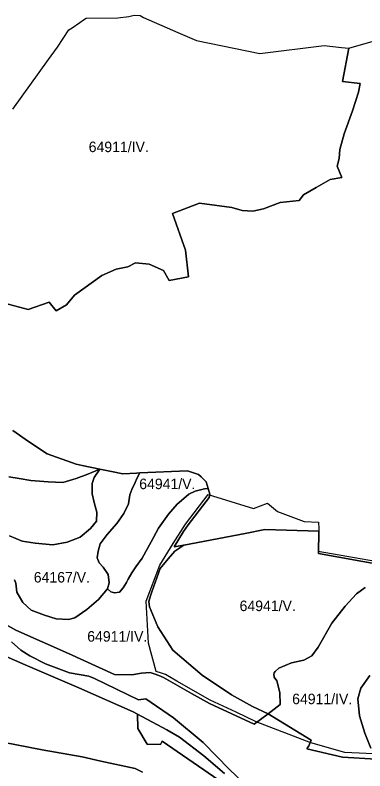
# Model space of a CAD drawing. Extents: x -521621 to -516761, y -1190184 to -1184927.
# Drawn here: x -520185 to -519686, y -1187011 to -1185932 of the extents above; entities that cross this region are included whole.
import ezdxf

# ---------------------------------------------------------------- set-up
doc = ezdxf.new("R2010")
doc.units = 0
doc.layers.add('BPEJ_s', color=7, linetype='Continuous')
doc.layers.add('odvodneni_s', color=7, linetype='Continuous')

msp = doc.modelspace()

# ---------------------------------------------------------------- linework, layer by layer
at = {"layer": 'BPEJ_s'}
for p, q in [((-520238.4, -1186779.9), (-520184.6, -1186810)), ((-520184.6, -1186810), (-520109.4, -1186843.3)), ((-520177.2, -1186838.5), (-520190.8, -1186826.8)), ((-520164.5, -1186846.6), (-520177.2, -1186838.5)), ((-520142.1, -1186858), (-520164.5, -1186846.6)), ((-520109.4, -1186843.3), (-520043.4, -1186873.2)), ((-520107.7, -1186870.7), (-520142.1, -1186858)), ((-520079.9, -1186875.5), (-520107.7, -1186870.7)), ((-520043.4, -1186873.2), (-520018.6, -1186873.6)), ((-520018.6, -1186873.6), (-520005, -1186871.4)), ((-520005, -1186871.4), (-519992.7, -1186870.6)), ((-519992.7, -1186870.6), (-519986.9, -1186872.5)), ((-519986.9, -1186872.5), (-519979.9, -1186874.8)), ((-520072.2, -1186878.9), (-520079.9, -1186875.5)), ((-520009.1, -1186909.3), (-520072.2, -1186878.9)), ((-519979.9, -1186874.8), (-519973.3, -1186877.6)), ((-519973.3, -1186877.6), (-519933.4, -1186900.2)), ((-519933.4, -1186900.2), (-519907.6, -1186914.7)), ((-519998.9, -1186908.1), (-520009.1, -1186909.3)), ((-519959.1, -1186935.4), (-519998.9, -1186908.1)), ((-519907.6, -1186914.7), (-519844, -1186944.4)), ((-520009.9, -1186950.2), (-520010.6, -1186930.1)), ((-520010.6, -1186930.1), (-519968.9, -1186952.1)), ((-519916.6, -1186970.3), (-519959.1, -1186935.4)), ((-519844, -1186944.4), (-519823.9, -1186929.6)), ((-519823.9, -1186929.6), (-519762.3, -1186967)), ((-519996.6, -1186972.9), (-520009.9, -1186950.2)), ((-519968.9, -1186952.1), (-519950.4, -1186962.7)), ((-519975.4, -1186968.4), (-519977.6, -1186973.3)), ((-519894.5, -1187024.1), (-519975.4, -1186968.4)), ((-519950.4, -1186962.7), (-519915.9, -1186989.2)), ((-519879.1, -1187008.9), (-519916.6, -1186970.3)), ((-519762.3, -1186967), (-519765.9, -1186974.9)), ((-519977.6, -1186973.3), (-519996.6, -1186972.9)), ((-519765.9, -1186974.9), (-519768.5, -1186979.4)), ((-519768.5, -1186979.4), (-519717.5, -1186991.5)), ((-519915.9, -1186989.2), (-519886.2, -1187014.6)), ((-519717.5, -1186991.5), (-519669.4, -1186994.1)), ((-519859.4, -1187027.5), (-519879.1, -1187008.9))]:
    msp.add_line(p, q, dxfattribs=at)
for points in [[(-520188.5, -1186066.3), (-520137.8, -1185995.6), (-520124.9, -1185977.6), (-520108.5, -1185953.2), (-520104.1, -1185950.1), (-520093.2, -1185942.6), (-520087.7, -1185938.8), (-520084.1, -1185936.3), (-520038.5, -1185935.8), (-520023.1, -1185934), (-520015.2, -1185932), (-520007, -1185932.6), (-520002, -1185935.2), (-519952.9, -1185956.6), (-519926.2, -1185968.3), (-519835.9, -1185987), (-519743.7, -1185975.4), (-519719.3, -1185978.2), (-519708.8, -1185979.4), (-519717.6, -1186026.9), (-519692.5, -1186029.7), (-519694.9, -1186042.2), (-519703.6, -1186068.6), (-519715.4, -1186101.7), (-519721.3, -1186123.8), (-519722.4, -1186136.5), (-519725.5, -1186147.7), (-519718.5, -1186163.7), (-519735.5, -1186166.9), (-519755.4, -1186178.3), (-519773.2, -1186188.4), (-519779.6, -1186196.5), (-519806.9, -1186199.7), (-519830.5, -1186208.5), (-519845.8, -1186211.7), (-519861, -1186210.9), (-519875.8, -1186206.8), (-519922.1, -1186200.5), (-519960.7, -1186215.1), (-519942.2, -1186267.5), (-519937.7, -1186305.7), (-519965.5, -1186310.8), (-519973.3, -1186296.6), (-519993.8, -1186287.6), (-520013.4, -1186285.8), (-520024.6, -1186291.4), (-520041.1, -1186294.9), (-520061.5, -1186303.9), (-520100.6, -1186331.8), (-520112.1, -1186345.7), (-520126.7, -1186354), (-520136.7, -1186342), (-520166.8, -1186352.1), (-520217.3, -1186338.9)], [(-520217.3, -1186338.9), (-520166.8, -1186352.1), (-520136.7, -1186342), (-520126.7, -1186354), (-520112.1, -1186345.7), (-520100.6, -1186331.8), (-520061.5, -1186303.9), (-520041.1, -1186294.9), (-520024.6, -1186291.4), (-520013.4, -1186285.8), (-519993.8, -1186287.6), (-519973.3, -1186296.6), (-519965.5, -1186310.8), (-519937.7, -1186305.7), (-519942.2, -1186267.5), (-519960.7, -1186215.1), (-519922.1, -1186200.5), (-519875.8, -1186206.8), (-519861, -1186210.9), (-519845.8, -1186211.7), (-519830.5, -1186208.5), (-519806.9, -1186199.7), (-519779.6, -1186196.5), (-519773.2, -1186188.4), (-519755.4, -1186178.3), (-519735.5, -1186166.9), (-519718.5, -1186163.7), (-519725.5, -1186147.7), (-519722.4, -1186136.5), (-519721.3, -1186123.8), (-519715.4, -1186101.7), (-519703.6, -1186068.6), (-519694.9, -1186042.2), (-519692.5, -1186029.7), (-519717.6, -1186026.9), (-519708.8, -1185979.4), (-519673.8, -1185969.3)], [(-520188.8, -1186525.2), (-520166.1, -1186540.8), (-520139.9, -1186558.3), (-520098, -1186573.1), (-520089.5, -1186574.9), (-520064.2, -1186580), (-520081.7, -1186587.3), (-520098.2, -1186593.7), (-520117.3, -1186599), (-520138.1, -1186598.5), (-520163.1, -1186596.4), (-520179.6, -1186593.7), (-520194.5, -1186591.1)], [(-519659.7, -1186717.4), (-519752.1, -1186700.7), (-519751.3, -1186668.7), (-519828.5, -1186666.5), (-519856.9, -1186671.8), (-519944.3, -1186688.5), (-519958.3, -1186691.2), (-519944.9, -1186669.1), (-519938.3, -1186659.7), (-519908.1, -1186620.4), (-519907, -1186615.8), (-519909.6, -1186607.6), (-519912.6, -1186598.3), (-519919.7, -1186591.1), (-519923.6, -1186587.6), (-519939.1, -1186582.5), (-520007.3, -1186585.5), (-520011.9, -1186585.7), (-520031.5, -1186586.8), (-520047.8, -1186583.3), (-520064.2, -1186580), (-520089.5, -1186574.9), (-520098, -1186573.1), (-520139.9, -1186558.3), (-520166.1, -1186540.8), (-520188.8, -1186525.2)], [(-520194.5, -1186591.1), (-520179.6, -1186593.7), (-520163.1, -1186596.4), (-520138.1, -1186598.5), (-520117.3, -1186599), (-520098.2, -1186593.7), (-520081.7, -1186587.3), (-520064.2, -1186580), (-520072.6, -1186592.1), (-520075.3, -1186600.6), (-520075.3, -1186615.6), (-520072.1, -1186629.9), (-520068.9, -1186641.7), (-520069.4, -1186654.5), (-520077.9, -1186665.1), (-520092.3, -1186677.4), (-520111, -1186684.3), (-520131.7, -1186688), (-520156.7, -1186685.9), (-520175.4, -1186683.2), (-520193.5, -1186675.2)], [(-520193.5, -1186675.2), (-520175.4, -1186683.2), (-520156.7, -1186685.9), (-520131.7, -1186688), (-520111, -1186684.3), (-520092.3, -1186677.4), (-520077.9, -1186665.1), (-520069.4, -1186654.5), (-520068.9, -1186641.7), (-520072.1, -1186629.9), (-520075.3, -1186615.6), (-520075.3, -1186600.6), (-520072.6, -1186592.1), (-520064.2, -1186580), (-520047.8, -1186583.3), (-520031.5, -1186586.8), (-520011.9, -1186585.7), (-520007.3, -1186585.5), (-520011.5, -1186593.3), (-520014.1, -1186599.1), (-520018.6, -1186609.1), (-520021.7, -1186616.8), (-520023.5, -1186629.8), (-520030.3, -1186643.7), (-520040.2, -1186657.6), (-520053.8, -1186673.3), (-520064, -1186686.6), (-520066.8, -1186697.1), (-520068, -1186707), (-520065.2, -1186713.8), (-520059.7, -1186720), (-520052.6, -1186730.5), (-520051.3, -1186742.3), (-520053.4, -1186751.1), (-520066.4, -1186766.1), (-520082.8, -1186780.7), (-520100, -1186792.6), (-520109.3, -1186794.8), (-520127, -1186793.7), (-520143.4, -1186788.6), (-520162.3, -1186781.6), (-520174.4, -1186770.6), (-520183.1, -1186755.9), (-520184.5, -1186742.9), (-520186.3, -1186738.1)], [(-520186.3, -1186738.1), (-520184.5, -1186742.9), (-520183.1, -1186755.9), (-520174.4, -1186770.6), (-520162.3, -1186781.6), (-520143.4, -1186788.6), (-520127, -1186793.7), (-520109.3, -1186794.8), (-520100, -1186792.6), (-520082.8, -1186780.7), (-520066.4, -1186766.1), (-520053.4, -1186751.1), (-520048.9, -1186755.4), (-520043.3, -1186756.8), (-520036.5, -1186755.6), (-520031.2, -1186749.4), (-520026.1, -1186741.8), (-520023.9, -1186737), (-520018.9, -1186728.1), (-520013, -1186719.4), (-520003.7, -1186707.3), (-519991.1, -1186684.1), (-519980.6, -1186664.5), (-519966.4, -1186644.4), (-519954.1, -1186630.3), (-519944.5, -1186622.1), (-519937.4, -1186616), (-519928.2, -1186611.6), (-519915, -1186608.2), (-519909.6, -1186607.6), (-519907, -1186615.8), (-519908.1, -1186620.4), (-519938.3, -1186659.7), (-519944.9, -1186669.1), (-519958.3, -1186691.2), (-519944.3, -1186688.5), (-519957.1, -1186697.4), (-519966.7, -1186708), (-519978.1, -1186722.1), (-519989.9, -1186755.5), (-519992, -1186761.1), (-519994.2, -1186769.2), (-519993.4, -1186776.5), (-519981.7, -1186805.4), (-519960.3, -1186838.5), (-519918.1, -1186874.4), (-519876.4, -1186902.2), (-519846.4, -1186918.8), (-519823.9, -1186929.6), (-519844, -1186944.4), (-519907.6, -1186914.7), (-519933.4, -1186900.2), (-519973.3, -1186877.6), (-519979.9, -1186874.8), (-519986.9, -1186872.5), (-519992.7, -1186870.6), (-520005, -1186871.4), (-520018.6, -1186873.6), (-520043.4, -1186873.2), (-520109.4, -1186843.3), (-520184.6, -1186810), (-520238.4, -1186779.9)], [(-519685.3, -1186749), (-519697.7, -1186758), (-519713.9, -1186775.6), (-519732.9, -1186799.9), (-519752.4, -1186834.2), (-519761.5, -1186846.6), (-519772.9, -1186852.8), (-519790.5, -1186856.6), (-519808.6, -1186864.3), (-519813.9, -1186869), (-519815.4, -1186871), (-519815.8, -1186873), (-519815.1, -1186876.9), (-519811.5, -1186882.4), (-519807.2, -1186899), (-519806.7, -1186916.2), (-519823.9, -1186929.6), (-519846.4, -1186918.8), (-519876.4, -1186902.2), (-519918.1, -1186874.4), (-519960.3, -1186838.5), (-519981.7, -1186805.4), (-519993.4, -1186776.5), (-519994.2, -1186769.2), (-519992, -1186761.1), (-519989.9, -1186755.5), (-519978.1, -1186722.1), (-519966.7, -1186708), (-519957.1, -1186697.4), (-519944.3, -1186688.5), (-519856.9, -1186671.8), (-519828.5, -1186666.5), (-519751.3, -1186668.7), (-519752.1, -1186700.7), (-519659.7, -1186717.4)], [(-519669.4, -1186994.1), (-519717.5, -1186991.5), (-519768.5, -1186979.4), (-519765.9, -1186974.9), (-519762.3, -1186967), (-519823.9, -1186929.6), (-519806.7, -1186916.2), (-519807.2, -1186899), (-519811.5, -1186882.4), (-519815.1, -1186876.9), (-519815.8, -1186873), (-519815.4, -1186871), (-519813.9, -1186869), (-519808.6, -1186864.3), (-519790.5, -1186856.6), (-519772.9, -1186852.8), (-519761.5, -1186846.6), (-519752.4, -1186834.2), (-519732.9, -1186799.9), (-519713.9, -1186775.6), (-519697.7, -1186758), (-519685.3, -1186749)], [(-520251, -1186825), (-520171.2, -1186859.6), (-520094.5, -1186892.4), (-520016.9, -1186926.5), (-520010.6, -1186930.1)], [(-519886.2, -1187014.6), (-519915.9, -1186989.2), (-519950.4, -1186962.7), (-519968.9, -1186952.1), (-520010.6, -1186930.1), (-520016.9, -1186926.5), (-520094.5, -1186892.4), (-520171.2, -1186859.6), (-520251, -1186825)], [(-520190.8, -1186826.8), (-520177.2, -1186838.5), (-520164.5, -1186846.6), (-520142.1, -1186858), (-520107.7, -1186870.7), (-520079.9, -1186875.5), (-520072.2, -1186878.9), (-520009.1, -1186909.3), (-519998.9, -1186908.1), (-519959.1, -1186935.4), (-519916.6, -1186970.3), (-519879.1, -1187008.9), (-519859.4, -1187027.5)], [(-520003.6, -1187012.6), (-520013.7, -1187007.7), (-520063.1, -1186996.9), (-520089.7, -1186990.9), (-520147, -1186980.8), (-520220.4, -1186966.5), (-520293.4, -1186945.2), (-520336.5, -1186932), (-520373.5, -1186911.8), (-520447.3, -1186874.7), (-520511, -1186853), (-520563, -1186835.4), (-520579.1, -1186831.3), (-520593, -1186831.3), (-520605.9, -1186833.5), (-520615.9, -1186835), (-520626.1, -1186836.2), (-520640.3, -1186839.8), (-520662.3, -1186849.2), (-520673.4, -1186852), (-520687.4, -1186857.7)], [(-519678.7, -1186874.7), (-519691.5, -1186892.8), (-519695.8, -1186908.1), (-519693.4, -1186932.4), (-519685.8, -1186957.2), (-519677.2, -1186978.6)], [(-519677.2, -1186978.6), (-519685.8, -1186957.2), (-519693.4, -1186932.4), (-519695.8, -1186908.1), (-519691.5, -1186892.8), (-519678.7, -1186874.7)], [(-520010.6, -1186930.1), (-520009.9, -1186950.2), (-519996.6, -1186972.9), (-519977.6, -1186973.3), (-519975.4, -1186968.4), (-519894.5, -1187024.1), (-519850.9, -1187069.2), (-519796.1, -1187106.2), (-519765.2, -1187130.4), (-519705.2, -1187168.1), (-519685.7, -1187175.9), (-519667.2, -1187182)], [(-520220.4, -1186966.5), (-520147, -1186980.8), (-520089.7, -1186990.9), (-520063.1, -1186996.9), (-520013.7, -1187007.7), (-520003.6, -1187012.6)]]:
    msp.add_lwpolyline(points, dxfattribs=at)
msp.add_lwpolyline([(-520053.4, -1186751.1), (-520051.3, -1186742.3), (-520052.6, -1186730.5), (-520059.7, -1186720), (-520065.2, -1186713.8), (-520068, -1186707), (-520066.8, -1186697.1), (-520064, -1186686.6), (-520053.8, -1186673.3), (-520040.2, -1186657.6), (-520030.3, -1186643.7), (-520023.5, -1186629.8), (-520021.7, -1186616.8), (-520018.6, -1186609.1), (-520014.1, -1186599.1), (-520011.5, -1186593.3), (-520007.3, -1186585.5), (-519939.1, -1186582.5), (-519923.6, -1186587.6), (-519919.7, -1186591.1), (-519912.6, -1186598.3), (-519909.6, -1186607.6), (-519915, -1186608.2), (-519928.2, -1186611.6), (-519937.4, -1186616), (-519944.5, -1186622.1), (-519954.1, -1186630.3), (-519966.4, -1186644.4), (-519980.6, -1186664.5), (-519991.1, -1186684.1), (-520003.7, -1186707.3), (-520013, -1186719.4), (-520018.9, -1186728.1), (-520023.9, -1186737), (-520026.1, -1186741.8), (-520031.2, -1186749.4), (-520036.5, -1186755.6), (-520043.3, -1186756.8), (-520048.9, -1186755.4)], close=True, dxfattribs=at)
at = {"layer": 'odvodneni_s'}
msp.add_lwpolyline([(-519663.4, -1186986.8), (-519714.2, -1186984.7), (-519763.1, -1186971), (-519841, -1186940.7), (-519869.5, -1186927.2), (-519906.9, -1186909.9), (-519954.6, -1186882.7), (-519970.7, -1186873.2), (-519976.2, -1186871.4), (-519983.7, -1186869), (-519995, -1186828.7), (-519998.3, -1186768.7), (-519978.8, -1186717.2), (-519959.4, -1186686.5), (-519942, -1186658.6), (-519909.4, -1186616.4), (-519844.7, -1186636.3), (-519824.9, -1186628.7), (-519810.6, -1186640.6), (-519772.6, -1186654.9), (-519751.9, -1186655.9), (-519751.7, -1186665.2), (-519752.3, -1186697.3), (-519659.4, -1186713.5)], dxfattribs=at)

# ---------------------------------------------------------------- texts
at = {"layer": 'BPEJ_s'}
for s, p in [('64911/IV.', (-520080.3, -1186127.6)), ('64941/V.', (-520008.1, -1186608.7)), ('64167/V.', (-520158.8, -1186742)), ('64941/V.', (-519864.7, -1186782.8)), ('64911/IV.', (-520082.4, -1186826.4)), ('64911/IV.', (-519789.6, -1186915.7))]:
    msp.add_text(s, height=15, dxfattribs=at).set_placement(p)

doc.saveas('drawing.dxf')
